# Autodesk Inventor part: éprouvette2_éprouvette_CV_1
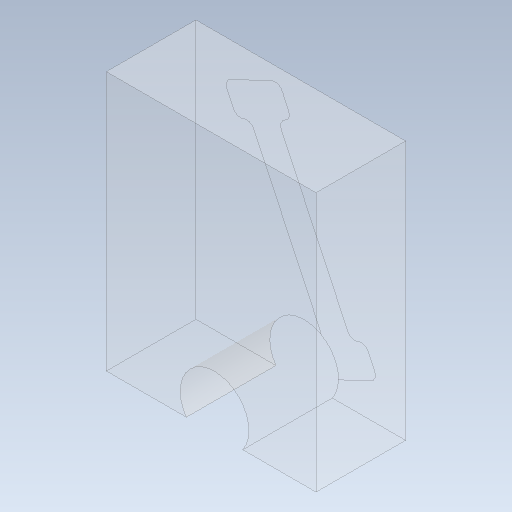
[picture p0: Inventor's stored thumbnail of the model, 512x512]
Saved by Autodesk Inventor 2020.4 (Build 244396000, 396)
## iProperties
Created: 2021-10
Part Number: éprouvette2_éprouvette_CV_1
Material: Générique
Document SubType Name: Modeling
Designer: mel
Density: 1 g/cm^3
Appearance: Par défaut
Author: mel
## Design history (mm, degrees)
node "éprouvette2_éprouvette_CV_Base"
feature "Sculpter3"
feature "Solide1::éprouvette2_éprouvette_CV_Base"
tag "FonctionRepérage1"
node "Solide1"
feature "éprouvette2_éprouvette_CV_Base_Corps"
feature "Surface3"
body "Srf3"
